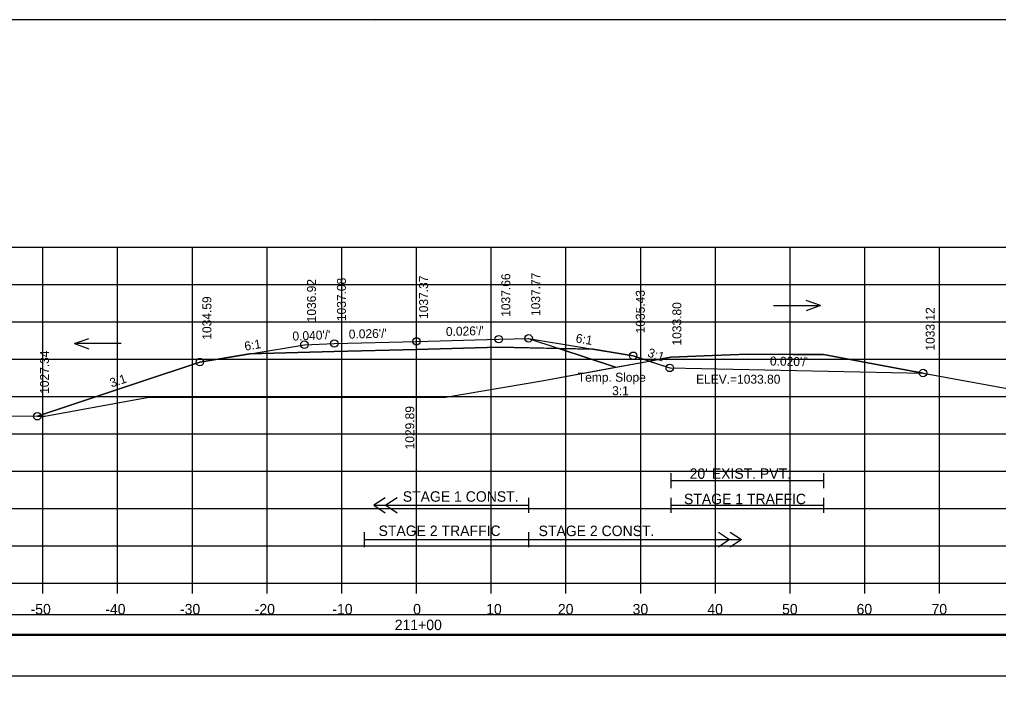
# Model space of a CAD drawing. Extents: x 1370565 to 1374448, y 301010 to 304637.
# Drawn here: x 1373315.7 to 1373446.7, y 302058.6 to 302147.8 of the extents above; entities that cross this region are included whole.
import ezdxf

# ---------------------------------------------------------------- set-up
doc = ezdxf.new("R2010")
doc.units = 0
for name, color, linetype in [('Default', 7, 'Continuous'), ('R_Alt Surface', 7, 'Continuous'), ('R_Axis', 7, 'Continuous'), ('R_Axis Annot', 7, 'Continuous'), ('R_Border', 7, 'Continuous'), ('R_Contours', 7, 'Continuous'), ('R_Drive', 7, 'Continuous'), ('R_Exist Surface', 7, 'Continuous'), ('R_Fin Surface', 7, 'Continuous'), ('R_Grid', 7, 'Continuous'), ('R_No Plot', 7, 'Continuous'), ('R_Water', 7, 'Continuous'), ('R_Water Annot', 7, 'Continuous'), ('R_Xsect Elev', 7, 'Continuous'), ('R_Xsect Slope', 7, 'Continuous')]:
    doc.layers.add(name, color=color, linetype=linetype)

msp = doc.modelspace()

# ---------------------------------------------------------------- linework, layer by layer
at = {"layer": 'Default'}
msp.add_lwpolyline([(1373219.61, 302065.35), (1373518.02, 302065.35), (1373518.02, 302068.06), (1373219.61, 302068.06)], close=True, dxfattribs=at)
at = {"layer": 'R_Alt Surface'}
for points in [[(1373346.48, 302103.01), (1373357.81, 302103.31), (1373368.81, 302103.6), (1373379.81, 302103.89), (1373392.47, 302103.64)], [(1373364.61, 302083.72), (1373363.11, 302082.72), (1373364.61, 302081.72)], [(1373363.11, 302082.72), (1373383.81, 302082.72)], [(1373366.21, 302083.72), (1373364.71, 302082.72), (1373366.21, 302081.72)], [(1373361.81, 302079.13), (1373361.81, 302077.13)], [(1373383.81, 302079.13), (1373383.81, 302077.13)], [(1373383.81, 302079.13), (1373383.81, 302077.13)], [(1373409.21, 302079.13), (1373410.71, 302078.13), (1373409.21, 302077.13)], [(1373410.8, 302079.13), (1373412.3, 302078.13), (1373410.8, 302077.13)], [(1373361.81, 302078.13), (1373383.81, 302078.13)], [(1373383.81, 302078.13), (1373412.3, 302078.13)]]:
    msp.add_lwpolyline(points, dxfattribs=at)
at = {"layer": 'R_Axis'}
for p, q in [((1373218.81, 302072.31), (1373518.81, 302072.31)), ((1373318.81, 302070.91), (1373318.81, 302072.31)), ((1373328.81, 302070.91), (1373328.81, 302072.31)), ((1373338.81, 302070.91), (1373338.81, 302072.31)), ((1373348.81, 302070.91), (1373348.81, 302072.31)), ((1373358.81, 302070.91), (1373358.81, 302072.31)), ((1373368.81, 302070.91), (1373368.81, 302072.31)), ((1373378.81, 302070.91), (1373378.81, 302072.31)), ((1373388.81, 302070.91), (1373388.81, 302072.31)), ((1373398.81, 302070.91), (1373398.81, 302072.31)), ((1373408.81, 302070.91), (1373408.81, 302072.31)), ((1373418.81, 302070.91), (1373418.81, 302072.31)), ((1373428.81, 302070.91), (1373428.81, 302072.31)), ((1373438.81, 302070.91), (1373438.81, 302072.31))]:
    msp.add_line(p, q, dxfattribs=at)
for points in [[(1373402.84, 302087.03), (1373402.84, 302085.03)], [(1373423.28, 302087.03), (1373423.28, 302085.03)], [(1373402.84, 302086.03), (1373423.28, 302086.03)], [(1373383.81, 302083.72), (1373383.81, 302081.72)], [(1373402.84, 302083.72), (1373402.84, 302081.72)], [(1373402.84, 302082.72), (1373423.28, 302082.72)], [(1373423.28, 302083.72), (1373423.28, 302081.72)]]:
    msp.add_lwpolyline(points, dxfattribs=at)
at = {"layer": 'R_Border'}
for p, q in [((1373210.81, 302147.77), (1373526.99, 302147.77)), ((1373363.33, 302147.51), (1373363.33, 302147.51)), ((1373363.33, 302147.51), (1373363.33, 302147.51))]:
    msp.add_line(p, q, dxfattribs=at)
at = {"layer": 'R_Contours'}
for p, q in [((1373395.44, 302101.2), (1373387.86, 302103.73)), ((1373392.47, 302103.64), (1373387.86, 302103.73)), ((1373387.86, 302103.73), (1373395.44, 302101.2)), ((1373346.48, 302103.01), (1373339.81, 302101.9)), ((1373395.44, 302101.2), (1373399.96, 302102.03)), ((1373399.96, 302102.03), (1373402.7, 302101.11)), ((1373402.7, 302101.11), (1373436.6, 302100.44))]:
    msp.add_line(p, q, dxfattribs=at)
for points in [[(1373387.86, 302103.73), (1373379.81, 302103.89), (1373368.81, 302103.6), (1373357.81, 302103.31), (1373346.48, 302103.01)], [(1373399.96, 302102.03), (1373397.81, 302102.74), (1373392.47, 302103.64)], [(1373436.6, 302100.44), (1373434.93, 302100.74), (1373423.28, 302102.9), (1373419.15, 302102.94), (1373413.14, 302102.97), (1373408.44, 302102.8), (1373402.84, 302102.55), (1373399.96, 302102.03)], [(1373339.81, 302101.9), (1373331.62, 302099.17), (1373318.07, 302094.65)], [(1373318.07, 302094.65), (1373319.07, 302094.65), (1373332.97, 302097.2), (1373353.08, 302097.16), (1373368.81, 302097.21), (1373372.67, 302097.22), (1373385.56, 302099.4), (1373395.44, 302101.2)]]:
    msp.add_lwpolyline(points, dxfattribs=at)
at = {"layer": 'R_Drive'}
msp.add_lwpolyline([(1373219.61, 302059.89), (1373518.02, 302059.89), (1373518.02, 302065.41), (1373219.61, 302065.41)], close=True, dxfattribs=at)
at = {"layer": 'R_Exist Surface'}
msp.add_lwpolyline([(1373218.81, 302086.33), (1373226.14, 302086.17), (1373229.56, 302086.44), (1373237.69, 302087.19), (1373237.85, 302087.23), (1373238.3, 302087.4), (1373257.32, 302094.17), (1373259.51, 302094.95), (1373319.07, 302094.65), (1373332.97, 302097.2), (1373353.08, 302097.16), (1373372.67, 302097.22), (1373385.56, 302099.4), (1373402.84, 302102.55), (1373408.44, 302102.8), (1373413.14, 302102.97), (1373419.15, 302102.94), (1373423.28, 302102.9), (1373434.93, 302100.74), (1373450.3, 302097.93), (1373478.87, 302097.85), (1373488.98, 302097.85), (1373498.87, 302097.81), (1373518.81, 302097.8)], dxfattribs=at)
at = {"layer": 'R_Fin Surface'}
msp.add_line((1373383.81, 302105.08), (1373395.44, 302101.2), dxfattribs=at)
msp.add_lwpolyline([(1373318.07, 302094.65), (1373331.62, 302099.17), (1373339.81, 302101.9), (1373353.81, 302104.23), (1373357.81, 302104.39), (1373368.81, 302104.68), (1373379.81, 302104.97), (1373383.81, 302105.08), (1373397.81, 302102.75), (1373402.7, 302101.12), (1373436.6, 302100.44)], dxfattribs=at)
at = {"layer": 'R_Grid'}
for p, q in [((1373218.81, 302117.31), (1373518.81, 302117.31)), ((1373318.81, 302072.31), (1373318.81, 302117.31)), ((1373328.81, 302072.31), (1373328.81, 302117.31)), ((1373338.81, 302072.31), (1373338.81, 302117.31)), ((1373348.81, 302072.31), (1373348.81, 302117.31)), ((1373358.81, 302072.31), (1373358.81, 302117.31)), ((1373368.81, 302072.31), (1373368.81, 302117.31)), ((1373378.81, 302072.31), (1373378.81, 302117.31)), ((1373388.81, 302072.31), (1373388.81, 302117.31)), ((1373398.81, 302072.31), (1373398.81, 302117.31)), ((1373408.81, 302072.31), (1373408.81, 302117.31)), ((1373418.81, 302072.31), (1373418.81, 302117.31)), ((1373428.81, 302072.31), (1373428.81, 302117.31)), ((1373438.81, 302072.31), (1373438.81, 302117.31)), ((1373218.81, 302112.31), (1373518.81, 302112.31)), ((1373218.81, 302107.31), (1373518.81, 302107.31)), ((1373218.81, 302102.31), (1373518.81, 302102.31)), ((1373218.81, 302097.31), (1373518.81, 302097.31)), ((1373218.81, 302092.31), (1373518.81, 302092.31)), ((1373218.81, 302087.31), (1373518.81, 302087.31)), ((1373218.81, 302082.31), (1373518.81, 302082.31)), ((1373218.81, 302077.31), (1373518.81, 302077.31)), ((1373218.81, 302072.31), (1373518.81, 302072.31))]:
    msp.add_line(p, q, dxfattribs=at)
at = {"layer": 'R_No Plot'}
msp.add_lwpolyline([(1373444.73, 302147.77), (1373464.35, 302147.77), (1373464.35, 302137.89), (1373480.47, 302137.89), (1373503.67, 302137.89), (1373503.67, 302105.22), (1373526.87, 302105.22), (1373526.99, 301942.31), (1373210.81, 301942.31), (1373210.81, 302147.77)], close=True, dxfattribs=at)
for centre in [(1373353.81, 302104.23), (1373357.81, 302104.39), (1373368.81, 302104.68), (1373379.81, 302104.97), (1373383.81, 302105.08), (1373339.81, 302101.9), (1373397.81, 302102.75), (1373402.7, 302101.12), (1373436.6, 302100.44), (1373318.07, 302094.65)]:
    msp.add_circle(centre, 0.5, dxfattribs=at)
at = {"layer": 'R_Water Annot'}
for p, q in [((1373422.87, 302109.47), (1373420.94, 302110.15)), ((1373416.58, 302109.47), (1373422.87, 302109.47)), ((1373422.87, 302109.47), (1373420.94, 302108.78)), ((1373323.02, 302104.37), (1373324.94, 302105.07)), ((1373329.3, 302104.37), (1373323.02, 302104.37)), ((1373323.02, 302104.37), (1373324.94, 302103.67))]:
    msp.add_line(p, q, dxfattribs=at)
at = {"layer": 'R_Xsect Elev'}
msp.add_line((1373368.81, 302087.21), (1373368.81, 302097.21), dxfattribs=at)

# ---------------------------------------------------------------- texts
at = {"layer": 'R_Axis Annot'}
for s, p in [("20' EXIST. PVT.", (1373405.36, 302086.27)), ('-50', (1373317.16, 302068.11)), ('-40', (1373327.16, 302068.11)), ('-30', (1373337.16, 302068.11)), ('-20', (1373347.16, 302068.11)), ('-10', (1373357.55, 302068.11)), ('0', (1373368.36, 302068.11)), ('10', (1373378.13, 302068.11)), ('20', (1373387.73, 302068.11)), ('30', (1373397.73, 302068.11)), ('40', (1373407.73, 302068.11)), ('50', (1373417.73, 302068.11)), ('60', (1373427.7, 302068.11)), ('70', (1373437.73, 302068.11)), ('211+00', (1373365.9, 302066.01))]:
    msp.add_text(s, height=1.4, dxfattribs=at).set_placement(p)
at = {"layer": 'R_Water'}
for s, p in [('STAGE 1 CONST.', (1373366.97, 302083.2)), ('STAGE 1 TRAFFIC', (1373404.6, 302082.87)), ('STAGE 2 TRAFFIC', (1373363.73, 302078.61)), ('STAGE 2 CONST.', (1373385.15, 302078.6))]:
    msp.add_text(s, height=1.4, dxfattribs=at).set_placement(p)
at = {"layer": 'R_Xsect Elev'}
for s, p in [('1036.92', (1373355.36, 302107.23)), ('1037.08', (1373359.36, 302107.39)), ('1037.37', (1373370.36, 302107.68)), ('1037.66', (1373381.36, 302107.97)), ('1037.77', (1373385.36, 302108.08)), ('1035.43', (1373399.36, 302105.75)), ('1034.59', (1373341.36, 302104.9)), ('1033.80', (1373404.25, 302104.12)), ('1033.12', (1373438.15, 302103.44)), ('1027.34', (1373319.62, 302097.65)), ('1029.89', (1373368.51, 302090.21))]:
    msp.add_text(s, height=1.2, rotation=90, dxfattribs=at).set_placement(p)
msp.add_text('ELEV.=1033.80', height=1.2, dxfattribs=at).set_placement((1373406.22, 302099.01))
at = {"layer": 'R_Xsect Slope'}
for s, rotation, p in [("0.040'/'", 2.2906, (1373352.23, 302104.77)), ("0.026'/'", 1.5109, (1373359.76, 302105.04)), ("0.026'/'", 1.5109, (1373372.76, 302105.39)), ('6:1', 9.4623, (1373345.88, 302103.42)), ('6:1', 350.5377, (1373390.05, 302104.55)), ('3:1', 341.5651, (1373399.63, 302102.67)), ("0.020'/'", 358.8542, (1373416.1, 302101.45)), ('3:1', 18.4349, (1373328, 302098.49)), ('Temp. Slope ', 0.0151, (1373390.4, 302099.27)), ('3:1', 0.0151, (1373394.99, 302097.47))]:
    msp.add_text(s, height=1.2, rotation=rotation, dxfattribs=at).set_placement(p)

doc.saveas('drawing.dxf')
